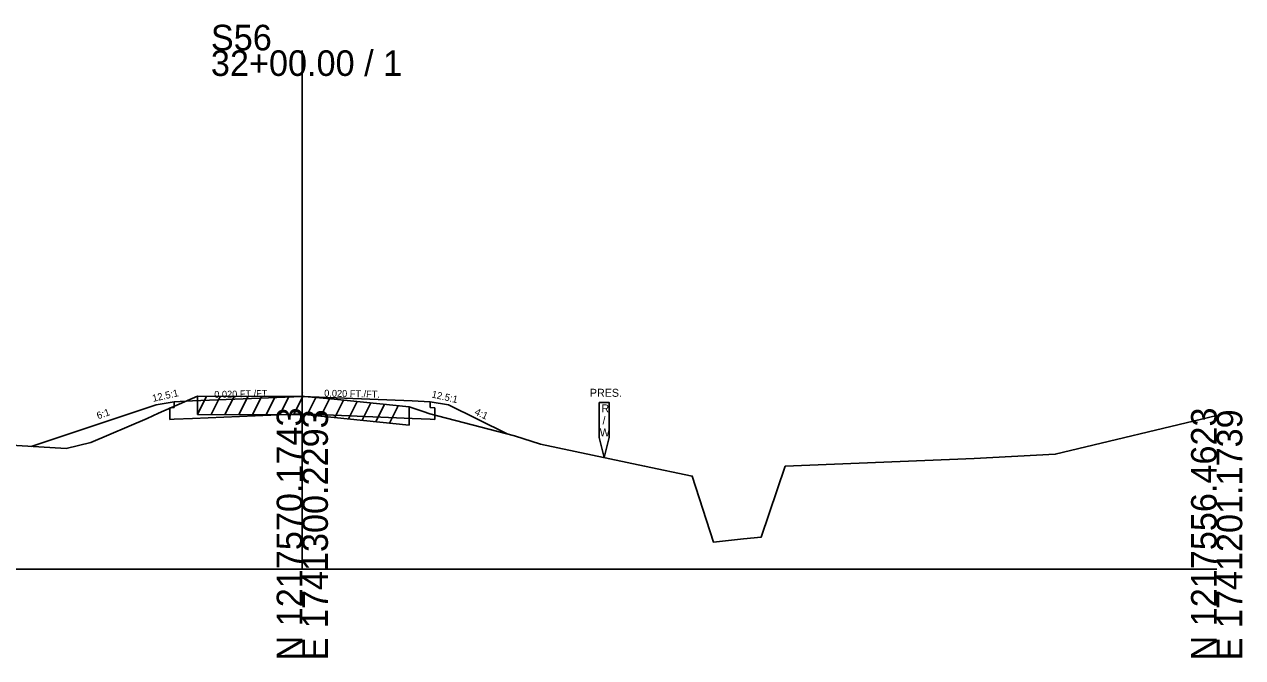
# Model space of a CAD drawing. Extents: x -26 to 1203, y -10 to 19541.
# Drawn here: x 69.6 to 202.8, y 6990.3 to 7059.6 of the extents above; entities that cross this region are included whole.
import ezdxf

# ---------------------------------------------------------------- set-up
doc = ezdxf.new("R2010")
doc.units = 0
for name, color, linetype in [('RD_GPK_XS_Cell', 7, 'Continuous'), ('RD_XS_Base', 7, 'Continuous'), ('RD_XS_EarthShd', 7, 'Continuous'), ('RD_XS_ExGround', 7, 'Continuous'), ('RD_XS_ExPaveRet', 7, 'Continuous'), ('RD_XS_ExRW', 7, 'Continuous'), ('RD_XS_Pave', 7, 'Continuous'), ('RD_XS_TX_Elev_EX', 7, 'Continuous'), ('RD_XS_TX_Slope', 7, 'Continuous')]:
    doc.layers.add(name, color=color, linetype=linetype)

msp = doc.modelspace()

# ---------------------------------------------------------------- linework, layer by layer
at = {"layer": 'RD_GPK_XS_Cell'}
for p, q in [((100, 7000), (100, 7056.78)), ((0, 7000), (100, 7000)), ((100, 7000), (200, 7000))]:
    msp.add_line(p, q, dxfattribs=at)
at = {"layer": 'RD_XS_Base'}
for p, q in [((86, 7017.68), (85.5, 7017.66)), ((85.5, 7016.39), (85.5, 7017.66)), ((86, 7017.68), (86, 7018.32)), ((114, 7017.68), (114, 7018.32)), ((114, 7017.68), (114.5, 7017.66)), ((114.5, 7016.39), (114.5, 7017.66)), ((86, 7016.41), (85.5, 7016.39)), ((86, 7016.41), (88, 7016.49)), ((88, 7016.49), (100, 7016.99)), ((112, 7016.49), (100, 7016.99)), ((114, 7016.41), (112, 7016.49)), ((114, 7016.41), (114.5, 7016.39))]:
    msp.add_line(p, q, dxfattribs=at)
at = {"layer": 'RD_XS_EarthShd'}
for p, q in [((84, 7017.98), (70.35, 7013.43)), ((86, 7018.32), (84, 7017.98)), ((114, 7018.32), (116, 7017.98)), ((116, 7017.98), (122.39, 7014.79))]:
    msp.add_line(p, q, dxfattribs=at)
at = {"layer": 'RD_XS_ExGround'}
msp.add_lwpolyline([(52.56, 7014.51), (74.16, 7013.2), (76.88, 7013.84), (83.02, 7016.47), (84.27, 7017.05), (88.54, 7018.93), (97.03, 7018.88), (100.25, 7018.91), (103.49, 7018.6), (111.67, 7017.76), (113.21, 7017.25), (113.95, 7016.98), (123.22, 7014.57), (126.04, 7013.69), (137.44, 7011.28), (142.64, 7010.18), (144.98, 7002.94), (148.24, 7003.3), (150.19, 7003.5), (152.81, 7011.25), (173.48, 7012.12), (182.34, 7012.57), (200, 7016.83)], dxfattribs=at)
at = {"layer": 'RD_XS_ExPaveRet'}
for p, q in [((88.54, 7016.93), (88.54, 7018.93)), ((88.54, 7016.93), (89.53, 7018.92)), ((90.04, 7016.92), (91.03, 7018.91)), ((91.54, 7016.91), (92.53, 7018.91)), ((93.04, 7016.9), (94.03, 7018.9)), ((94.54, 7016.9), (95.53, 7018.89)), ((96.04, 7016.89), (97.03, 7018.88)), ((97.54, 7016.89), (98.54, 7018.9)), ((99.04, 7016.9), (100.04, 7018.91)), ((100.54, 7016.89), (101.49, 7018.79)), ((102.04, 7016.74), (102.99, 7018.65)), ((103.54, 7016.59), (104.49, 7018.5)), ((105.04, 7016.44), (105.99, 7018.34)), ((106.54, 7016.29), (107.49, 7018.19)), ((108.04, 7016.13), (108.99, 7018.04)), ((109.54, 7015.98), (110.49, 7017.88)), ((111.67, 7017.76), (111.67, 7015.76)), ((88.54, 7016.93), (97.03, 7016.88)), ((97.03, 7016.88), (100.25, 7016.91)), ((100.25, 7016.91), (103.49, 7016.6)), ((103.49, 7016.6), (111.67, 7015.76))]:
    msp.add_line(p, q, dxfattribs=at)
at = {"layer": 'RD_XS_ExRW'}
msp.add_lwpolyline([(132.45, 7018.24), (133.55, 7018.24), (133.55, 7014.41), (133, 7012.22), (132.45, 7014.41)], close=True, dxfattribs=at)
at = {"layer": 'RD_XS_Pave'}
for p, q in [((86, 7018.32), (88, 7018.4)), ((88, 7018.4), (100, 7018.9)), ((112, 7018.4), (100, 7018.9)), ((114, 7018.32), (112, 7018.4))]:
    msp.add_line(p, q, dxfattribs=at)

# ---------------------------------------------------------------- texts
at = {"layer": 'RD_GPK_XS_Cell'}
for s, p in [('S56', (90, 7056.78)), ('32+00.00 / 1', (90, 7053.98))]:
    msp.add_text(s, height=2.8, dxfattribs=at).set_placement(p)
for s, p in [('N 1217570.1743', (100, 6990)), ('E 1741300.2293', (102.8, 6990)), ('N 1217556.4623', (200, 6990)), ('E 1741201.1739', (202.8, 6990))]:
    msp.add_text(s, height=2.8, rotation=90, dxfattribs=at).set_placement(p)
at = {"layer": 'RD_XS_ExRW'}
for s, p in [('PRES.', (131.45, 7018.86)), ('R', (132.71, 7017.15)), ('/', (132.83, 7015.83)), ('W', (132.53, 7014.52))]:
    msp.add_text(s, height=0.875, dxfattribs=at).set_placement(p)
at = {"layer": 'RD_XS_TX_Elev_EX'}
msp.add_text('847.46', height=0.1, rotation=90, dxfattribs=at).set_placement((100.1, 7018.91))
at = {"layer": 'RD_XS_TX_Slope'}
for s, height, rotation, p in [('12.5:1', 0.778, 12.7511, (83.69, 7018.3)), ('0.020 FT./FT.', 0.7518, 1.1916, (90.38, 7018.74)), ('0.020 FT./FT.', 0.7518, 358.8084, (102.39, 7018.89)), ('12.5:1', 0.778, 347.2489, (114.09, 7018.8)), ('6:1', 0.778, 19.3982, (77.67, 7016.39)), ('4:1', 0.778, 335.081, (118.77, 7016.95))]:
    msp.add_text(s, height=height, rotation=rotation, dxfattribs=at).set_placement(p)

doc.saveas('drawing.dxf')
